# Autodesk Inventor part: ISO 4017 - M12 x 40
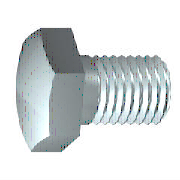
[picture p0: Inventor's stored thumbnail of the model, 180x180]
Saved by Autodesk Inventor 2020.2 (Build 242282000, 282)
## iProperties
Manager: www.cadconsulting.pl
Company: Fabian Stasiak CAD Consulting
Created: 2010-02
Part Number: ISO 4017 - M12 x 40
Material: Stal nierdzewna, 440C
Description: Wkręty z łbem sześciokątnym
Document SubType Name: Modeling
Standard: ISO 4017
Designer: F.Stasiak
Standard Revision: Third edition 1999-08-15
Standards Organization: ISO
Language: pl-PL
Size Designation: M12 x 40
Categories: <MemberInstance><Categories><Category DisplayName="Mocowania" InternalName="e4da775c-781d-43d5-af7c-5136215cf5a6" Mnemonic="FSTN"><Category DisplayName="Śruby"
Density: 7.75 g/cm^3
Appearance: Metal-Stal
IsCustomPart: 0
Author: F.Stasiak
Subject: Zbiór ćwiczeń. Autodesk Inventor 2020. Kurs podstawowy
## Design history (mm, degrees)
sketch "Sketch1"
  geometry: L1 (0, 8.315)-(0, 6); L2 (5.3, 6)-(40, 6); L3 (40, 6)-(40, 0); L4 (40, 0)-(-0.6, 0); L5 (-8.72, 0)-(48.12, 0) reference; L6 (-0.6, 0)-(-0.6, 8.315); L7 (-0.6, 8.315)-(0, 8.315); L8 (5.3, 6)-(4.226, 6); L9 (4.226, 6)-(0, 6); L10 (0, -1.663)-(0, 9.978) reference
  constraints: 16 end point, 2 collinear, 2 perpendicular, 1 parallel
  dimensions: "d0" = 40 distance between parallel lines of L3 L1 (= NLG); "d1" = 34.7 distance from line of L2.start L3 (= GEL); "d2" = 12 diameter of L2 L4 (= GD); "d9" = 0.6001 distance between parallel lines of L6 L1 (computed from SD); "d10" = 16.63 diameter of L7 L4 (= SD2); "d13" = 1.07364 distance of L2.start L8.end (computed from GAL); "d14" = 12 diameter of L9 L4 (= BDM)
revolve "Body" sketch "Sketch1" stored, may be unused: angle "d12" = 90 deg
sketch "Sketch2"
  geometry: L1 (0, 10.392)-(9, 5.196); L2 (9, 5.196)-(9, -5.196); L3 (9, -5.196)-(0, -10.392); L4 (0, -10.392)-(-9, -5.196); L5 (-9, -5.196)-(-9, 5.196); L6 (-9, 5.196)-(0, 10.392); 2 further points
  constraints: 12 end point, 1 coincident, 1 vertical, 11 other
  dimensions: "d11" = 18 distance between parallel lines of L5 L2 (= SW)
extrude "Head" join sketch "Sketch2" distance "d3" = 6.9 (= KOH - SD); taper "d4" = 0 deg
sketch "Sketch4"
  geometry: L1 (-7.5, 9)-(-7.5, 10.392); L2 (-7.5, 10.392)-(-6.696, 10.392); L3 (-6.696, 10.392)-(-7.5, 9); L4 (-8.88, 0)-(0.78, 0) reference; L5 (-0.6, 10.392)-(-7.5, 10.392) reference; L6 (-7.5, 5.196)-(-7.5, 10.392) reference
  constraints: 6 end point, 2 collinear, 1 perpendicular, 1 vertical
  dimensions: "d5" = 30 deg angle of L3 L1 (= ANG1); "d19" = 18 diameter of L1.start L4 (= SW0)
revolve "Chamfer1" sketch "Sketch4" stored, may be unused: angle "d21" = 90 deg
feature "Thread" dims "d15" = 34.7 (= GEL), "d16" = 0
chamfer "Chamfer2" distance "d6" = 1.07354 (= -0.5 x SPD + 0.5 x GD); stored, may be unused: second distance "d7" = 1.07364 (computed from GUL), angle "d55" = 45 deg
workplane "Work Plane1"
body "Solid1"
other parameters: "NLG" = 40 [user parameter; used in 1 equation term], "GD" = 12 (= NND) [user parameter; used in 2 equation terms], "BDM" = 12 (= NND) [user parameter; used in 1 equation term], "KOH" = 7.5 [user parameter; used in 1 equation term], "GEL" = 34.7 [user parameter; used in 2 equation terms], "SW" = 18 [user parameter; used in 2 equation terms], "SW0" = 18 (= SW) [user parameter; used in 1 equation term], "SPD" = 9.85293 (= NND - 1.2269 x PTC) [user parameter; used in 1 equation term], "SD2" = 16.63 [user parameter; used in 2 equation terms], "SD" = 0.6 [user parameter; used in 2 equation terms], "ANG1" = 30 deg [user parameter; used in 1 equation term], "GAL" = 1.07354 (= 0.61345 x PTC) [user parameter; used in 1 equation term], "GUL" = 1.07354 (= 0.61345 x PTC) [user parameter; used in 1 equation term], "d8" = 0, "RR" = 0.6 [user parameter], "d57" = 0, "d58" = 0, "TPU" = 5.71429 (computed from PTC) [user parameter], "GD1" = 9.85293 (= THREADDIA - 1.2269 x PTC) [user parameter], "THREADDIA" = 12 [user parameter; used in 1 equation term], "SDH" = 16.63 (= SD2) [user parameter], "SDHG" = 5.3 [user parameter], "TOA" = 30 deg [user parameter], "PTC" = 1.75 [user parameter; used in 5 equation terms], "NND" = 12 [user parameter; used in 3 equation terms], "E0" = 20.79 [user parameter]
